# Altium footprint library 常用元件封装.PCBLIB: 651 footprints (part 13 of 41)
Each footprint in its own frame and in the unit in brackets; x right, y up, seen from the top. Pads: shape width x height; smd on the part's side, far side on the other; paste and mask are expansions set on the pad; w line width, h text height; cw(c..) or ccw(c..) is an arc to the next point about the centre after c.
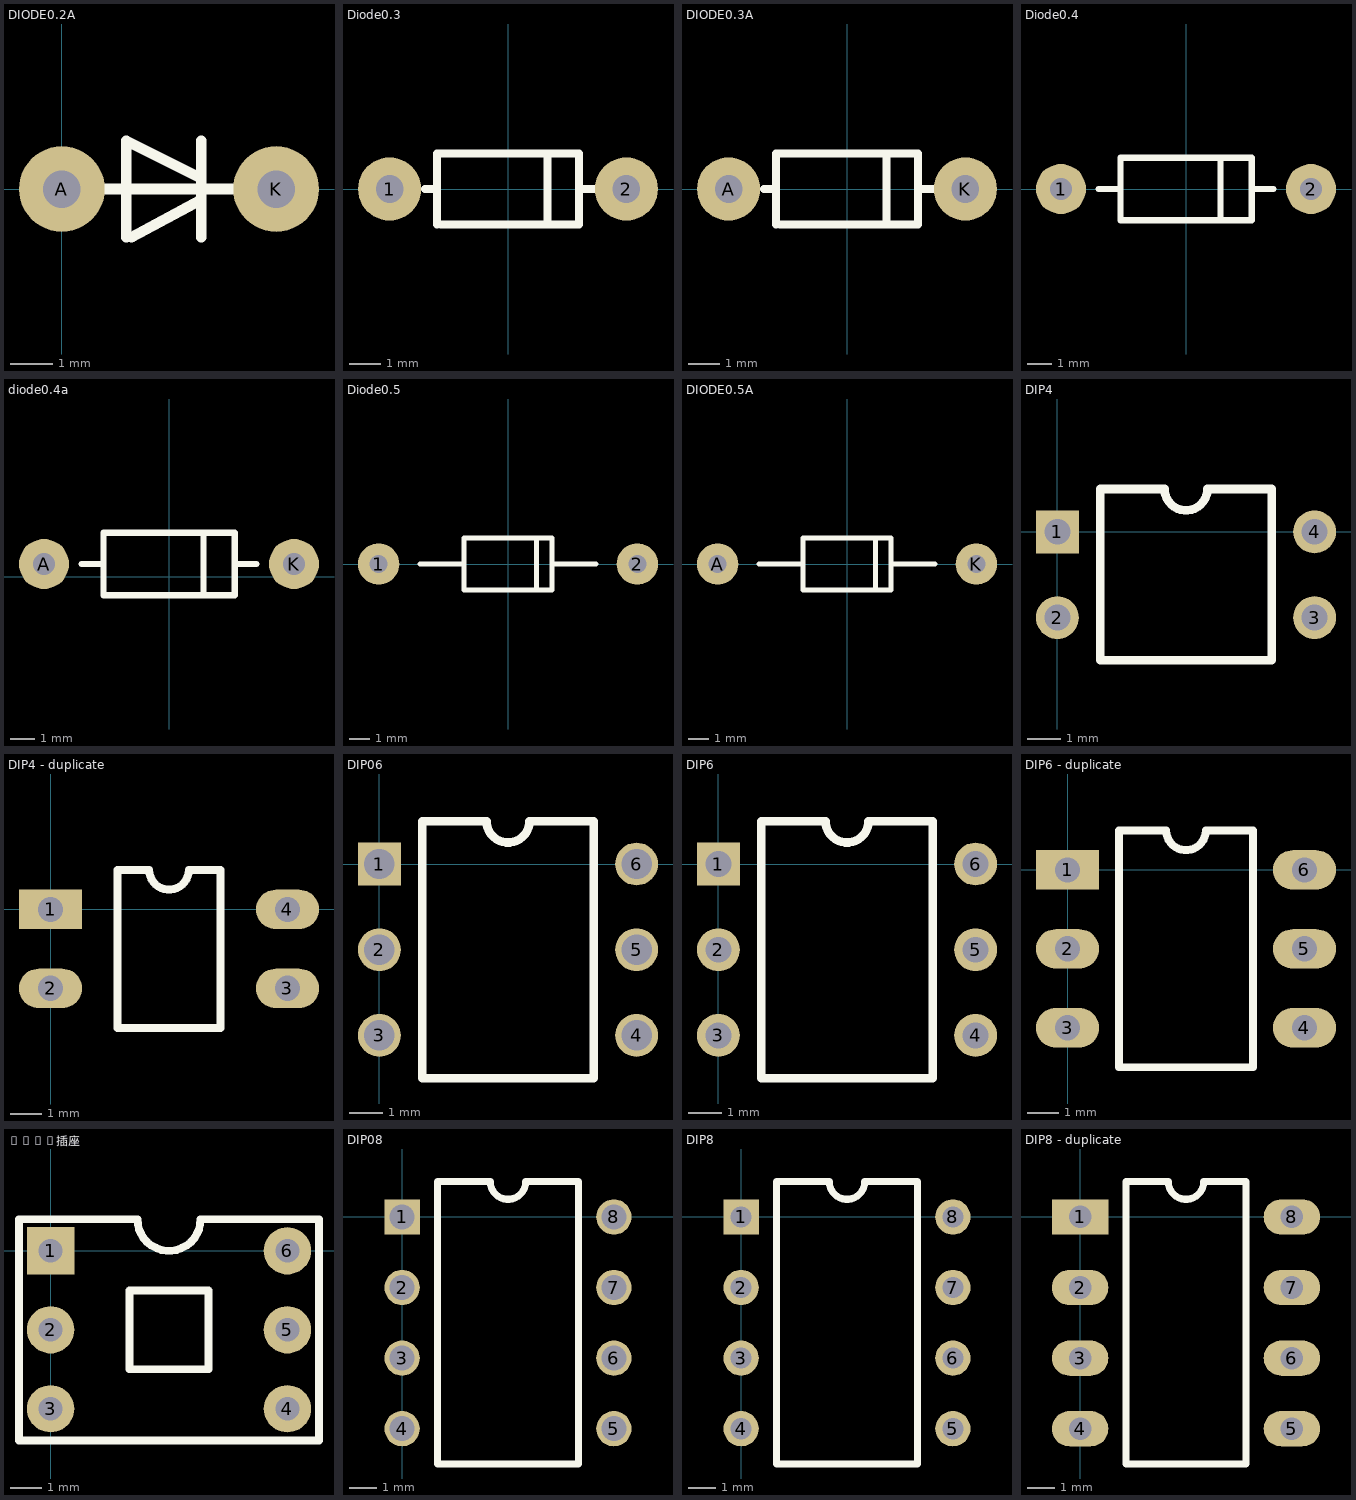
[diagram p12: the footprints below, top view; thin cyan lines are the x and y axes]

## DIODE0.2A [mil]
pads (2):
  round 80 hole 35: A(0,0) K(200,0)
TopOverlay:
  lines w10: 35,0 160,0 ; 60,-45 60,45 130,10 ; 65,-45 130,-10 ; 130,-45 130,45

## Diode0.3 [mil]
pads (2):
  round 80 hole 35: 1(-150,0) 2(150,0)
TopOverlay:
  lines w10: -105,0 -90,0 ; -90,-45 -90,45 90,45 90,-45 -85,-45 ; 50,-45 50,45 ; 90,0 110,0

## DIODE0.3A [mil]
pads (2):
  round 80 hole 35: A(-150,0) K(150,0)
TopOverlay:
  lines w10: -105,0 -90,0 ; -90,-45 -90,45 90,45 90,-45 -85,-45 ; 50,-45 50,45 ; 90,0 110,0

## Diode0.4 [mil]
pads (2):
  round 80 hole 35: 1(-200,0) 2(200,0)
TopOverlay:
  lines w10: -140,0 -105,0 ; 55,-50 55,50 ; 105,0 140,0 ; -105,-50 -105,-10 -105,50 105,50 105,-50 -105,-50

## diode0.4a [mil]
pads (2):
  round 80 hole 35: A(-200,20) K(200,20)
TopOverlay:
  lines w10: -140,20 -105,20 ; 55,-30 55,70 ; 105,20 140,20 ; -105,-30 -105,10 -105,70 105,70 105,-30 -105,-30

## Diode0.5 [mil]
pads (2):
  round 80 hole 35: 1(-250,0) 2(250,0)
TopOverlay:
  lines w10: -170,0 -85,0 ; 55,-50 55,50 ; 85,0 170,0 ; -85,0 -85,-50 85,-50 85,50 -85,50 -85,0

## DIODE0.5A [mil]
pads (2):
  round 80 hole 35: A(-250,0) K(250,0)
TopOverlay:
  lines w10: -170,0 -85,0 ; 55,-50 55,50 ; 85,0 170,0 ; -85,0 -85,-50 85,-50 85,50 -85,50 -85,0

## DIP4 [mil]
pads (4):
  rect 50x50 hole 30: 1(0,0)
  round 50 hole 30: 2(0,-100) 3(300,-100) 4(300,0)
TopOverlay:
  lines w10: 50,-150 50,50 125,50 ccw(c150,50) 175,50 250,50 250,-150 50,-150

## DIP4 - duplicate [mil]
pads (4):
  rect 80x50 hole 32: 1(0,0)
  oval 80x50 hole 32: 2(0,-100) 3(300,-100) 4(300,0)
TopOverlay:
  lines w10: 85,-150 85,50 125,50 ccw(c150,50) 175,50 215,50 215,-150 85,-150

## DIP06 [mm]
pads (6):
  rect 1.27x1.27 hole 0.9: 1(0,0)
  round 1.27 hole 0.9: 2(0,-2.54) 3(0,-5.08) 4(7.62,-5.08) 5(7.62,-2.54) 6(7.62,0)
TopOverlay:
  lines w0.254: 1.27,-6.35 1.27,1.27 3.175,1.27 ccw(c3.81,1.27) 4.445,1.27 6.35,1.27 6.35,-6.35 1.27,-6.35

## DIP6 [mil]
pads (6):
  rect 50x50 hole 30: 1(0,0)
  round 50 hole 30: 2(0,-100) 3(0,-200) 4(300,-200) 5(300,-100) 6(300,0)
TopOverlay:
  lines w10: 50,-250 50,50 125,50 ccw(c150,50) 175,50 250,50 250,-250 50,-250

## DIP6 - duplicate [mil]
pads (6):
  rect 80x50 hole 32: 1(0,0)
  oval 80x50 hole 32: 2(0,-100) 3(0,-200) 4(300,-200) 5(300,-100) 6(300,0)
TopOverlay:
  lines w10: 65,-250 65,50 125,50 ccw(c150,50) 175,50 235,50 235,-250 65,-250

## DIP6插座 [mil]
pads (6):
  rect 60x60 hole 30: 1(0,0)
  round 60 hole 30: 2(0,-100) 3(0,-200) 4(300,-200) 5(300,-100) 6(300,0)
TopOverlay:
  lines w10: -40,-240 340,-240 340,40 190,40 cw(c150,40) 110,40 -40,40 -40,-240 ; 100,-150 100,-50 200,-50 200,-150 100,-150

## DIP08 [mm]
pads (8):
  rect 1.27x1.27 hole 0.9: 1(0,0)
  round 1.27 hole 0.9: 2(0,-2.54) 3(0,-5.08) 4(0,-7.62) 5(7.62,-7.62) 6(7.62,-5.08) 7(7.62,-2.54) 8(7.62,0)
TopOverlay:
  lines w0.254: 1.27,-8.89 6.35,-8.89 6.35,1.27 4.445,1.27 cw(c3.81,1.27) 3.175,1.27 1.27,1.27 1.27,-8.89

## DIP8 [mil]
pads (8):
  rect 50x50 hole 30: 1(0,0)
  round 50 hole 30: 2(0,-100) 3(0,-200) 4(0,-300) 5(300,-300) 6(300,-200) 7(300,-100) 8(300,0)
TopOverlay:
  lines w10: 50,-350 250,-350 250,50 175,50 cw(c150,50) 125,50 50,50 50,-350

## DIP8 - duplicate [mil]
pads (8):
  rect 80x50 hole 32: 1(0,0)
  oval 80x50 hole 32: 2(0,-100) 3(0,-200) 4(0,-300) 5(300,-300) 6(300,-200) 7(300,-100) 8(300,0)
TopOverlay:
  lines w10: 65,-350 65,50 125,50 ccw(c150,50) 175,50 235,50 235,-350 65,-350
